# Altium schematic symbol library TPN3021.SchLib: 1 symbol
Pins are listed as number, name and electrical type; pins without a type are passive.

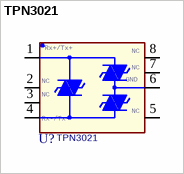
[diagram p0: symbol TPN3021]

## TPN3021
designator U?
footprint ST_SO8
pins: 1 Rx+ / Tx+, 2 NC, 3 NC1, 4 Rx- / Tx-, 5 NC2, 6 GND, 7 NC3, 8 NC4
